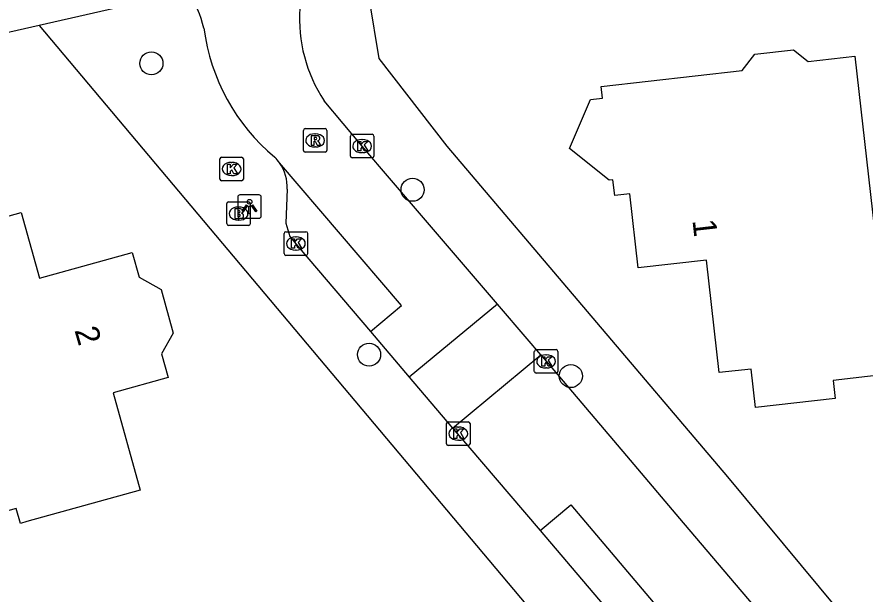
# Model space of a CAD drawing. Extents: x 161772 to 163123, y 383092 to 383917.
# Drawn here: x 162012.54 to 162048.54, y 383440.9 to 383465.41 of the extents above; entities that cross this region are included whole.
import ezdxf

# ---------------------------------------------------------------- set-up
doc = ezdxf.new("R2010")
doc.units = 0
for name, color, linetype in [('IMGEO_Boom', 7, 'Continuous'), ('IMGEO_Brandkraan', 7, 'Continuous'), ('IMGEO_Kolk', 7, 'Continuous'), ('IMGEO_Lichtpunt', 7, 'Continuous'), ('IMGEO_Pand', 7, 'Continuous'), ('IMGEO_Pand_nummerreeks', 7, 'Continuous'), ('IMGEO_Rijbaan_lokaal_open', 7, 'Continuous'), ('IMGEO_Rioolput', 7, 'Continuous'), ('IMGEO_Voetpad_gesloten', 7, 'Continuous'), ('IMGEO_Voetpad_open', 7, 'Continuous')]:
    doc.layers.add(name, color=color, linetype=linetype)

msp = doc.modelspace()

# ---------------------------------------------------------------- linework, layer by layer
at = {"layer": 'IMGEO_Boom'}
for centre in [(162018.245, 383463.439), (162029.331, 383458.07), (162027.487, 383451.069), (162036.051, 383450.159)]:
    msp.add_circle(centre, 0.489, dxfattribs=at)
at = {"layer": 'IMGEO_Brandkraan'}
for p, q in [((162021.444, 383456.632), (162021.444, 383457.484)), ((162021.519, 383457.558), (162022.371, 383457.558)), ((162021.932, 383457.338), (162021.957, 383457.338)), ((162022.445, 383457.484), (162022.445, 383456.632)), ((162022.371, 383456.558), (162021.519, 383456.558)), ((162021.955, 383456.778), (162021.93, 383456.778))]:
    msp.add_line(p, q, dxfattribs=at)
for points in [[(162021.444, 383456.632), (162021.444, 383457.484)], [(162021.519, 383457.558), (162022.371, 383457.558)], [(162021.792, 383457.258), (162021.792, 383456.858), (162022.005, 383456.858)], [(162022.023, 383457.258), (162021.792, 383457.258)], [(162022.445, 383457.484), (162022.445, 383456.632)], [(162021.971, 383457.177), (162021.917, 383457.177), (162021.917, 383457.101)], [(162021.917, 383457.101), (162021.97, 383457.101)], [(162021.979, 383457.025), (162021.917, 383457.025), (162021.917, 383456.944)], [(162021.917, 383456.944), (162021.979, 383456.944)], [(162022.371, 383456.558), (162021.519, 383456.558)]]:
    msp.add_lwpolyline(points, dxfattribs=at)
for centre, radius, start, end in [((162021.521, 383457.482), 0.0765, 91.552, 178.448), ((162021.521, 383457.482), 0.0765, 91.552, 178.448), ((162022.027, 383457.113), 0.145, 59.4692, 91.5367), ((162022.052, 383457.16), 0.0922, 285.5137, 58.1501), ((162022.369, 383457.482), 0.0765, 1.552, 88.448), ((162022.369, 383457.482), 0.0765, 1.552, 88.448), ((162021.972, 383457.139), 0.0379, 267.8285, 90.9355), ((162021.98, 383456.984), 0.0404, 269.8759, 90.5077), ((162022.011, 383457.109), 0.251, 268.6676, 293.5347), ((162022.057, 383456.968), 0.105, 301.3115, 78.989), ((162021.521, 383456.634), 0.0765, 181.552, 268.448), ((162021.521, 383456.634), 0.0765, 181.552, 268.448), ((162022.369, 383456.634), 0.0765, 271.552, 358.448), ((162022.369, 383456.634), 0.0765, 271.552, 358.448)]:
    msp.add_arc(centre, radius, start, end, dxfattribs=at)
for centre, major_axis, ratio, start_param, end_param in [((162021.931, 383457.058), (-0.387, 0.002), 0.722429, 4.712389, 7.853982), ((162021.956, 383457.058), (-0.39, 0.002), 0.717154, 1.570796, 4.712389)]:
    msp.add_ellipse(centre, major_axis=major_axis, ratio=ratio, start_param=start_param, end_param=end_param, dxfattribs=at)
at = {"layer": 'IMGEO_Kolk'}
for p, q in [((162026.691, 383459.502), (162026.691, 383460.354)), ((162026.766, 383460.428), (162027.618, 383460.428)), ((162027.179, 383460.208), (162027.204, 383460.208)), ((162027.692, 383460.354), (162027.692, 383459.502)), ((162021.15, 383458.528), (162021.15, 383459.38)), ((162021.225, 383459.454), (162022.077, 383459.454)), ((162022.151, 383459.38), (162022.151, 383458.528)), ((162027.618, 383459.428), (162026.766, 383459.428)), ((162027.202, 383459.648), (162027.177, 383459.648)), ((162021.638, 383459.234), (162021.663, 383459.234)), ((162021.661, 383458.674), (162021.636, 383458.674)), ((162022.077, 383458.454), (162021.225, 383458.454)), ((162023.878, 383455.36), (162023.878, 383456.212)), ((162023.953, 383456.286), (162024.805, 383456.286)), ((162024.879, 383456.212), (162024.879, 383455.36)), ((162024.366, 383456.066), (162024.391, 383456.066)), ((162024.389, 383455.506), (162024.364, 383455.506)), ((162024.805, 383455.286), (162023.953, 383455.286)), ((162034.502, 383450.357), (162034.502, 383451.209)), ((162034.577, 383451.283), (162035.429, 383451.283)), ((162035.503, 383451.209), (162035.503, 383450.357)), ((162034.99, 383451.063), (162035.015, 383451.063)), ((162035.013, 383450.503), (162034.988, 383450.503)), ((162035.429, 383450.283), (162034.577, 383450.283)), ((162030.845, 383448.214), (162031.697, 383448.214)), ((162030.77, 383447.288), (162030.77, 383448.14)), ((162031.258, 383447.994), (162031.283, 383447.994)), ((162031.771, 383448.14), (162031.771, 383447.288)), ((162031.697, 383447.214), (162030.845, 383447.214)), ((162031.281, 383447.434), (162031.256, 383447.434))]:
    msp.add_line(p, q, dxfattribs=at)
for points in [[(162026.691, 383459.502), (162026.691, 383460.354)], [(162026.766, 383460.428), (162027.618, 383460.428)], [(162027.012, 383460.128), (162027.135, 383460.128), (162027.135, 383459.977), (162027.265, 383460.128), (162027.429, 383460.128), (162027.283, 383459.977), (162027.436, 383459.728), (162027.284, 383459.728), (162027.199, 383459.892), (162027.135, 383459.825), (162027.135, 383459.728), (162027.012, 383459.728), (162027.012, 383460.128)], [(162027.692, 383460.354), (162027.692, 383459.502)], [(162021.15, 383458.528), (162021.15, 383459.38)], [(162021.225, 383459.454), (162022.077, 383459.454)], [(162022.151, 383459.38), (162022.151, 383458.528)], [(162027.618, 383459.428), (162026.766, 383459.428)], [(162021.471, 383459.154), (162021.594, 383459.154), (162021.594, 383459.003), (162021.724, 383459.154), (162021.888, 383459.154), (162021.742, 383459.003), (162021.895, 383458.754), (162021.743, 383458.754), (162021.658, 383458.918), (162021.594, 383458.851), (162021.594, 383458.754), (162021.471, 383458.754), (162021.471, 383459.154)], [(162022.077, 383458.454), (162021.225, 383458.454)], [(162023.878, 383455.36), (162023.878, 383456.212)], [(162023.953, 383456.286), (162024.805, 383456.286)], [(162024.879, 383456.212), (162024.879, 383455.36)], [(162024.199, 383455.986), (162024.322, 383455.986), (162024.322, 383455.835), (162024.452, 383455.986), (162024.616, 383455.986), (162024.47, 383455.835), (162024.623, 383455.586), (162024.471, 383455.586), (162024.386, 383455.75), (162024.322, 383455.683), (162024.322, 383455.586), (162024.199, 383455.586), (162024.199, 383455.986)], [(162024.805, 383455.286), (162023.953, 383455.286)], [(162034.502, 383450.357), (162034.502, 383451.209)], [(162034.577, 383451.283), (162035.429, 383451.283)], [(162035.503, 383451.209), (162035.503, 383450.357)], [(162034.823, 383450.983), (162034.946, 383450.983), (162034.946, 383450.832), (162035.076, 383450.983), (162035.24, 383450.983), (162035.094, 383450.832), (162035.247, 383450.583), (162035.095, 383450.583), (162035.01, 383450.747), (162034.946, 383450.68), (162034.946, 383450.583), (162034.823, 383450.583), (162034.823, 383450.983)], [(162035.429, 383450.283), (162034.577, 383450.283)], [(162030.845, 383448.214), (162031.697, 383448.214)], [(162030.77, 383447.288), (162030.77, 383448.14)], [(162031.091, 383447.914), (162031.214, 383447.914), (162031.214, 383447.763), (162031.344, 383447.914), (162031.508, 383447.914), (162031.362, 383447.763), (162031.515, 383447.514), (162031.363, 383447.514), (162031.278, 383447.678), (162031.214, 383447.611), (162031.214, 383447.514), (162031.091, 383447.514), (162031.091, 383447.914)], [(162031.771, 383448.14), (162031.771, 383447.288)], [(162031.697, 383447.214), (162030.845, 383447.214)]]:
    msp.add_lwpolyline(points, dxfattribs=at)
for centre, start, end in [((162026.768, 383460.352), 91.552, 178.448), ((162026.768, 383460.352), 91.552, 178.448), ((162027.616, 383460.352), 1.552, 88.448), ((162027.616, 383460.352), 1.552, 88.448), ((162021.227, 383459.378), 91.552, 178.448), ((162021.227, 383459.378), 91.552, 178.448), ((162022.075, 383459.378), 1.552, 88.448), ((162022.075, 383459.378), 1.552, 88.448), ((162026.768, 383459.504), 181.552, 268.448), ((162026.768, 383459.504), 181.552, 268.448), ((162027.616, 383459.504), 271.552, 358.448), ((162027.616, 383459.504), 271.552, 358.448), ((162021.227, 383458.53), 181.552, 268.448), ((162021.227, 383458.53), 181.552, 268.448), ((162022.075, 383458.53), 271.552, 358.448), ((162022.075, 383458.53), 271.552, 358.448), ((162023.955, 383456.21), 91.552, 178.448), ((162023.955, 383456.21), 91.552, 178.448), ((162024.803, 383456.21), 1.552, 88.448), ((162024.803, 383456.21), 1.552, 88.448), ((162023.955, 383455.362), 181.552, 268.448), ((162023.955, 383455.362), 181.552, 268.448), ((162024.803, 383455.362), 271.552, 358.448), ((162024.803, 383455.362), 271.552, 358.448), ((162034.579, 383451.207), 91.552, 178.448), ((162034.579, 383451.207), 91.552, 178.448), ((162035.427, 383451.207), 1.552, 88.448), ((162035.427, 383451.207), 1.552, 88.448), ((162034.579, 383450.359), 181.552, 268.448), ((162034.579, 383450.359), 181.552, 268.448), ((162035.427, 383450.359), 271.552, 358.448), ((162035.427, 383450.359), 271.552, 358.448), ((162030.847, 383448.138), 91.552, 178.448), ((162030.847, 383448.138), 91.552, 178.448), ((162031.695, 383448.138), 1.552, 88.448), ((162031.695, 383448.138), 1.552, 88.448), ((162030.847, 383447.29), 181.552, 268.448), ((162030.847, 383447.29), 181.552, 268.448), ((162031.695, 383447.29), 271.552, 358.448), ((162031.695, 383447.29), 271.552, 358.448)]:
    msp.add_arc(centre, 0.0765, start, end, dxfattribs=at)
for centre, major_axis, ratio, start_param, end_param in [((162027.178, 383459.928), (-0.387, 0.002), 0.722429, 4.712389, 7.853982), ((162027.203, 383459.928), (-0.39, 0.002), 0.717154, 1.570796, 4.712389), ((162021.637, 383458.954), (-0.387, 0.002), 0.722429, 4.712389, 7.853982), ((162021.662, 383458.954), (-0.39, 0.002), 0.717154, 1.570796, 4.712389), ((162024.365, 383455.786), (-0.387, 0.002), 0.722429, 4.712389, 7.853982), ((162024.39, 383455.786), (-0.39, 0.002), 0.717154, 1.570796, 4.712389), ((162034.989, 383450.783), (-0.387, 0.002), 0.722429, 4.712389, 7.853982), ((162035.014, 383450.783), (-0.39, 0.002), 0.717154, 1.570796, 4.712389), ((162031.257, 383447.714), (-0.387, 0.002), 0.722429, 4.712389, 7.853982), ((162031.282, 383447.714), (-0.39, 0.002), 0.717154, 1.570796, 4.712389)]:
    msp.add_ellipse(centre, major_axis=major_axis, ratio=ratio, start_param=start_param, end_param=end_param, dxfattribs=at)
at = {"layer": 'IMGEO_Lichtpunt'}
for p, q in [((162021.912, 383457.762), (162021.912, 383456.955)), ((162021.912, 383457.762), (162021.912, 383456.955)), ((162022.814, 383457.857), (162022.006, 383457.857)), ((162022.814, 383457.857), (162022.006, 383457.857)), ((162022.908, 383456.955), (162022.908, 383457.762)), ((162022.908, 383456.955), (162022.908, 383457.762)), ((162022.006, 383456.861), (162022.814, 383456.861)), ((162022.006, 383456.861), (162022.814, 383456.861))]:
    msp.add_line(p, q, dxfattribs=at)
for points in [[(162022.286, 383457.426), (162022.325, 383457.398), (162022.137, 383457.136), (162022.099, 383457.163), (162022.286, 383457.426)], [(162022.388, 383457.378), (162022.435, 383457.378), (162022.435, 383457.056), (162022.388, 383457.056), (162022.388, 383457.378)], [(162022.498, 383457.398), (162022.536, 383457.425), (162022.723, 383457.163), (162022.684, 383457.135), (162022.498, 383457.398)]]:
    msp.add_lwpolyline(points, dxfattribs=at)
msp.add_circle((162022.411, 383457.56), 0.0994, dxfattribs=at)
for centre, start, end in [((162022.006, 383457.762), 90, 180), ((162022.006, 383457.762), 90, 180), ((162022.814, 383457.762), 0, 90), ((162022.814, 383457.762), 0, 90), ((162022.006, 383456.955), 180, 270), ((162022.006, 383456.955), 180, 270), ((162022.814, 383456.955), 270, 0), ((162022.814, 383456.955), 270, 360)]:
    msp.add_arc(centre, 0.0946, start, end, dxfattribs=at)
at = {"layer": 'IMGEO_Pand'}
for points in [[(162049.497, 383450.238), (162047.191, 383449.977), (162047.277, 383449.211), (162043.888, 383448.828), (162043.704, 383450.457), (162042.352, 383450.305), (162041.811, 383455.087), (162038.905, 383454.759), (162038.55, 383457.9), (162037.915, 383457.828), (162037.84, 383458.491), (162037.685, 383458.474), (162035.988, 383459.826), (162036.891, 383461.899), (162037.401, 383461.956), (162037.344, 383462.464), (162043.319, 383463.14), (162043.869, 383463.829), (162045.505, 383464.014), (162046.125, 383463.521), (162048.105, 383463.744), (162049.434, 383451.991)], [(162012.958, 383443.979), (162012.687, 383443.904), (162012.51, 383444.539), (162009.13, 383443.6), (162008.206, 383446.925), (162007.74, 383446.796), (162006.778, 383450.26), (162005.442, 383455.069), (162005.989, 383455.221), (162006.174, 383455.938), (162007.502, 383456.307), (162008.272, 383455.872), (162012.722, 383457.108), (162013.498, 383454.316), (162017.433, 383455.409), (162017.726, 383454.356), (162018.654, 383453.831), (162019.168, 383451.983), (162018.671, 383451.104), (162018.951, 383450.098), (162016.627, 383449.452), (162017.775, 383445.318), (162012.958, 383443.979)]]:
    msp.add_lwpolyline(points, dxfattribs=at)
at = {"layer": 'IMGEO_Rijbaan_lokaal_open'}
for points in [[(162032.937, 383453.211), (162028.008, 383458.961), (162027.191, 383459.927), (162025.575, 383461.853)], [(162027.544, 383452.055), (162028.859, 383453.162), (162023.689, 383459.213)], [(162032.937, 383453.211), (162029.195, 383450.109)], [(162034.776, 383451.058), (162034.192, 383451.747), (162032.937, 383453.211)], [(162027.544, 383452.055), (162029.195, 383450.109)], [(162031.033, 383447.948), (162034.776, 383451.058)], [(162034.776, 383451.058), (162038.41, 383446.77), (162040.822, 383443.925), (162060.745, 383420.481)], [(162029.195, 383450.109), (162031.033, 383447.948)], [(162031.033, 383447.948), (162031.679, 383447.192), (162034.081, 383444.38), (162034.744, 383443.6)], [(162034.744, 383443.6), (162036.054, 383444.697), (162040.018, 383440.006), (162043.957, 383435.348), (162047.931, 383430.647), (162046.657, 383429.59)]]:
    msp.add_lwpolyline(points, dxfattribs=at)
for centre, radius, start, end in [((162015.728, 383463.75), 4.894, 13.9433, 34.1779), ((162030.885, 383465.34), 6.353, 176.095, 213.2943), ((162028.96, 383466.022), 8.552, 187.3439, 230.1844), ((162022.192, 383458.142), 1.84, 35.5828, 45.4229)]:
    msp.add_arc(centre, radius, start, end, dxfattribs=at)
at = {"layer": 'IMGEO_Rioolput'}
for p, q in [((162024.696, 383459.743), (162024.696, 383460.595)), ((162024.771, 383460.669), (162025.623, 383460.669)), ((162025.697, 383460.595), (162025.697, 383459.743)), ((162025.184, 383460.449), (162025.209, 383460.449)), ((162025.207, 383459.889), (162025.182, 383459.889)), ((162025.623, 383459.669), (162024.771, 383459.669))]:
    msp.add_line(p, q, dxfattribs=at)
for points in [[(162024.696, 383459.743), (162024.696, 383460.595)], [(162024.771, 383460.669), (162025.623, 383460.669)], [(162025.697, 383460.595), (162025.697, 383459.743)], [(162025.285, 383460.367), (162025.033, 383460.369), (162025.033, 383459.969)], [(162025.033, 383459.969), (162025.157, 383459.969), (162025.157, 383460.131), (162025.168, 383460.131)], [(162025.211, 383460.288), (162025.157, 383460.288), (162025.157, 383460.207)], [(162025.157, 383460.207), (162025.209, 383460.207)], [(162025.215, 383460.102), (162025.286, 383459.969), (162025.426, 383459.969), (162025.361, 383460.095)], [(162025.623, 383459.669), (162024.771, 383459.669)]]:
    msp.add_lwpolyline(points, dxfattribs=at)
for centre, radius, start, end in [((162024.773, 383460.593), 0.0765, 91.552, 178.448), ((162024.773, 383460.593), 0.0765, 91.552, 178.448), ((162025.621, 383460.593), 0.0765, 1.552, 88.448), ((162025.621, 383460.593), 0.0765, 1.552, 88.448), ((162025.167, 383460.078), 0.0533, 26.0293, 88.6989), ((162025.193, 383460.396), 0.19, 274.7715, 282.9687), ((162025.217, 383460.192), 0.0964, 77.0061, 93.1865), ((162025.231, 383460.249), 0.0378, 276.6634, 79.6772), ((162025.284, 383460.257), 0.109, 350.3612, 89.416), ((162025.282, 383460.257), 0.112, 277.5842, 350.9817), ((162025.266, 383460.042), 0.108, 29.5134, 73.7905), ((162024.773, 383459.745), 0.0765, 181.552, 268.448), ((162024.773, 383459.745), 0.0765, 181.552, 268.448), ((162025.621, 383459.745), 0.0765, 271.552, 358.448), ((162025.621, 383459.745), 0.0765, 271.552, 358.448)]:
    msp.add_arc(centre, radius, start, end, dxfattribs=at)
for centre, major_axis, ratio, start_param, end_param in [((162025.183, 383460.169), (-0.387, 0.002), 0.722429, 4.712389, 7.853982), ((162025.208, 383460.169), (-0.39, 0.002), 0.717154, 1.570796, 4.712389)]:
    msp.add_ellipse(centre, major_axis=major_axis, ratio=ratio, start_param=start_param, end_param=end_param, dxfattribs=at)
at = {"layer": 'IMGEO_Voetpad_gesloten'}
for points in [[(162019.777, 383466.499), (162013.474, 383465.049)], [(162027.495, 383466.15), (162027.9, 383463.647), (162030.791, 383459.92), (162042.704, 383445.878), (162056.737, 383428.976), (162069.531, 383413.985), (162082.036, 383400.151), (162085.851, 383396.183), (162119.667, 383362.459), (162125.116, 383357.112)], [(162013.474, 383465.049), (162067.97, 383400.221)], [(162024.006, 383458.096), (162023.946, 383456.646), (162024.128, 383456.084), (162024.525, 383455.612), (162027.544, 383452.055)], [(162034.744, 383443.6), (162046.657, 383429.59)]]:
    msp.add_lwpolyline(points, dxfattribs=at)
msp.add_arc((162022.258, 383458.203), 1.751, 356.4804, 35.207, dxfattribs=at)
at = {"layer": 'IMGEO_Voetpad_open'}
msp.add_lwpolyline([(162013.474, 383465.049), (162000.265, 383462.051), (162000.295, 383461.907), (161996.785, 383460.931), (161992.404, 383459.714), (161973.318, 383454.411), (161972.09, 383452.564)], dxfattribs=at)

# ---------------------------------------------------------------- texts
at = {"layer": 'IMGEO_Pand_nummerreeks'}
for s, rotation, p in [('1', 276.4483, (162041.213, 383456.773)), ('2', 286.1762, (162014.974, 383452.108))]:
    msp.add_text(s, height=1, rotation=rotation, dxfattribs=at).set_placement(p)

doc.saveas('drawing.dxf')
